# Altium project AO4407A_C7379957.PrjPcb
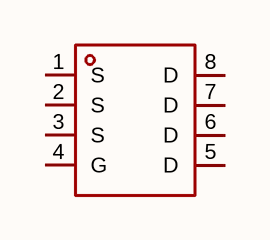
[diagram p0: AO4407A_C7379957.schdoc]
1 sheet, 1 parts. Net scope: global (net labels, ports and power ports of the same name join across sheets).

## Sheet AO4407A_C7379957.schdoc
size 127 x 101 mm

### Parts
Q?  ao4407a_c7379957  [SOP-8_L4.9-W3.9-P1.27-LS6.0-BL]  (value not drawn)

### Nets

Not connected (* = marked no-connect by the designer): Q? 1(S) 2(S) 3(S) 4(G) 5(D) 6(D) 7(D) 8(D)

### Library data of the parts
Q? = ao4407a_c7379957: 数量:1个P沟道;漏源电压(Vdss):30V;连续漏极电流(Id):12A;导通电阻(RDS(on)):9mΩ@10V;耗散功率(Pd):2W;; Manufacturer: MSKSEMI(美森科); AddInBom: yes; ModelId: 75c24a7891ee4dd6bdac16a7163ff87e; ModelName: SOP-8_L4.9-W3.9-P1.27-LS6.0-BL-1; ModelTransform: 192.913,236.22,0,0,0,0,-0.393,2.749,0; Number: 1个P沟道; Drain to Source Voltage: 30V; Current - Continuous Drain(Id): 12A; Pd - Power Dissipation: 2W; Gate Charge(Qg): 34nC@10V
